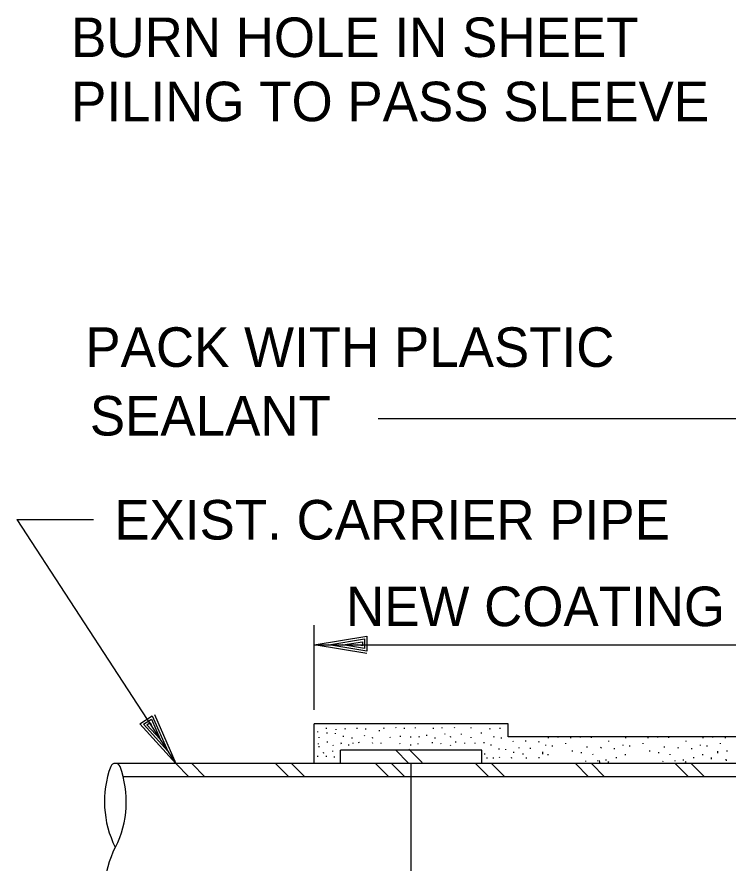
# Model space of a CAD drawing. Extents: x 22411.4 to 22495.4, y 22369.6 to 22415.
# Drawn here: x 22423.849 to 22427.205, y 22392.769 to 22396.764 of the extents above; entities that cross this region are included whole.
import ezdxf

# ---------------------------------------------------------------- set-up
doc = ezdxf.new("R2010")
doc.units = 0
for name, color, linetype in [('Level 1', 7, 'Continuous'), ('Level 2', 7, 'Continuous'), ('Level 4', 7, 'Continuous'), ('Level 8', 7, 'Continuous')]:
    doc.layers.add(name, color=color, linetype=linetype)

msp = doc.modelspace()

# ---------------------------------------------------------------- linework, layer by layer
at = {"layer": 'Level 1'}
for p, q in [((22425.251, 22393.4924), (22425.251, 22393.8919)), ((22425.251, 22393.7989), (22427.4581, 22393.7989)), ((22426.3069, 22393.7989), (22426.3069, 22393.7989)), ((22426.3762, 22393.7989), (22426.3762, 22393.7989))]:
    msp.add_line(p, q, dxfattribs=at)
msp.add_lwpolyline([(22425.5004, 22393.7575), (22425.251, 22393.7989), (22425.5004, 22393.8402), (22425.5004, 22393.7695), (22425.3204, 22393.7989), (22425.4897, 22393.8269), (22425.4897, 22393.7815), (22425.387, 22393.7989), (22425.479, 22393.8135), (22425.479, 22393.7949), (22425.4564, 22393.7989)], dxfattribs=at)
for centre, radius, start, end in [((22424.3136, 22393.2159), 0.0235, 20.1936, 159.8064), ((22424.7418, 22393.0584), 0.4798, 159.8064, 206.6071), ((22423.8853, 22393.0584), 0.4798, 333.3929, 20.1936), ((22424.7418, 22392.6286), 0.4798, 153.3929, 200.1919)]:
    msp.add_arc(centre, radius, start, end, dxfattribs=at)
at = {"layer": 'Level 2'}
for p, q in [((22425.5528, 22394.8684), (22427.4697, 22394.8684)), ((22423.8491, 22394.3903), (22424.2107, 22394.3903)), ((22423.8491, 22394.3903), (22424.5994, 22393.2392)), ((22426.1677, 22393.4267), (22425.251, 22393.4267)), ((22425.251, 22393.2392), (22425.251, 22393.4267)), ((22426.1677, 22393.3642), (22426.1677, 22393.4267)), ((22426.3069, 22393.3642), (22426.1677, 22393.3642)), ((22432.6119, 22393.3642), (22426.3069, 22393.3642)), ((22425.376, 22393.2392), (22425.376, 22393.3017)), ((22426.0427, 22393.3017), (22425.376, 22393.3017)), ((22426.0427, 22393.2392), (22426.0427, 22393.3017)), ((22429.4594, 22393.2392), (22424.3136, 22393.2392)), ((22425.7094, 22392.4475), (22425.7094, 22393.2392)), ((22429.4594, 22393.1767), (22424.3503, 22393.1767))]:
    msp.add_line(p, q, dxfattribs=at)
for points in [[(22424.4979, 22393.4707), (22424.5994, 22393.2392), (22424.4286, 22393.4255), (22424.4878, 22393.4641), (22424.5615, 22393.2973), (22424.4456, 22393.4239), (22424.4836, 22393.4486), (22424.5251, 22393.3532), (22424.4626, 22393.4222), (22424.4782, 22393.4324), (22424.4873, 22393.4112)], [(22427.1329, 22393.3613), (22427.1327, 22393.3642)]]:
    msp.add_lwpolyline(points, dxfattribs=at)
at = {"layer": 'Level 8'}
for p, q in [((22425.2696, 22393.3864), (22425.2693, 22393.3904)), ((22425.31, 22393.4025), (22425.3096, 22393.4066)), ((22425.3557, 22393.3971), (22425.3553, 22393.4012)), ((22425.3987, 22393.3998), (22425.3983, 22393.4039)), ((22425.4551, 22393.4025), (22425.4548, 22393.4066)), ((22425.4954, 22393.3998), (22425.4951, 22393.4039)), ((22425.56, 22393.3918), (22425.5596, 22393.3958)), ((22425.5815, 22393.4025), (22425.5811, 22393.4066)), ((22425.6379, 22393.4052), (22425.6376, 22393.4093)), ((22425.6782, 22393.4025), (22425.6779, 22393.4066)), ((22425.7293, 22393.4052), (22425.729, 22393.4093)), ((22425.8153, 22393.4025), (22425.815, 22393.4066)), ((22425.8556, 22393.4052), (22425.8553, 22393.4093)), ((22425.9147, 22393.4052), (22425.9144, 22393.4093)), ((22425.9927, 22393.4052), (22425.9924, 22393.4093)), ((22426.0814, 22393.3998), (22426.0811, 22393.4039)), ((22426.1298, 22393.4025), (22426.1295, 22393.4066)), ((22425.275, 22393.3595), (22425.2747, 22393.3635)), ((22425.3126, 22393.381), (22425.3123, 22393.3851)), ((22425.353, 22393.3783), (22425.3526, 22393.3824)), ((22425.3906, 22393.3648), (22425.3903, 22393.3689)), ((22425.4309, 22393.3568), (22425.4306, 22393.3609)), ((22425.4901, 22393.3675), (22425.4897, 22393.3716)), ((22425.5277, 22393.3568), (22425.5274, 22393.3609)), ((22425.611, 22393.3595), (22425.6107, 22393.3636)), ((22425.6594, 22393.3649), (22425.6591, 22393.369)), ((22425.7078, 22393.3622), (22425.7074, 22393.3663)), ((22425.7481, 22393.3622), (22425.7478, 22393.3663)), ((22425.783, 22393.3702), (22425.7827, 22393.3743)), ((22425.8233, 22393.3568), (22425.823, 22393.3609)), ((22425.869, 22393.3756), (22425.8687, 22393.3797)), ((22425.8959, 22393.3622), (22425.8956, 22393.3663)), ((22425.947, 22393.3756), (22425.9467, 22393.3797)), ((22425.9927, 22393.3595), (22425.9924, 22393.3636)), ((22426.0411, 22393.381), (22426.0408, 22393.3851)), ((22426.1002, 22393.3622), (22426.0999, 22393.3663)), ((22426.1352, 22393.3568), (22426.1348, 22393.3609)), ((22426.3575, 22393.3585), (22426.3572, 22393.3626)), ((22426.4627, 22393.3585), (22426.4623, 22393.3626)), ((22426.5605, 22393.3598), (22426.5602, 22393.3639)), ((22426.7223, 22393.3585), (22426.7219, 22393.3626)), ((22426.8274, 22393.3585), (22426.8271, 22393.3626)), ((22426.9253, 22393.3598), (22426.9249, 22393.3639)), ((22427.087, 22393.3585), (22427.0867, 22393.3626)), ((22427.1922, 22393.3585), (22427.1918, 22393.3626)), ((22425.2723, 22393.3299), (22425.272, 22393.334)), ((22425.275, 22393.3164), (22425.2747, 22393.3205)), ((22425.3153, 22393.3379), (22425.315, 22393.342)), ((22425.3422, 22393.3218), (22425.3419, 22393.3259)), ((22425.3798, 22393.3326), (22425.3795, 22393.3366)), ((22425.3798, 22393.3299), (22425.3795, 22393.334)), ((22425.4148, 22393.3245), (22425.4145, 22393.3286)), ((22425.4363, 22393.3326), (22425.436, 22393.3367)), ((22425.4632, 22393.3353), (22425.4628, 22393.3393)), ((22425.5277, 22393.3326), (22425.5274, 22393.3367)), ((22425.568, 22393.3326), (22425.5677, 22393.3367)), ((22425.6567, 22393.3299), (22425.6564, 22393.334)), ((22425.7078, 22393.3245), (22425.7074, 22393.3286)), ((22425.7427, 22393.3299), (22425.7424, 22393.334)), ((22425.8099, 22393.3353), (22425.8096, 22393.3394)), ((22425.8502, 22393.3299), (22425.8499, 22393.334)), ((22425.8959, 22393.3218), (22425.8956, 22393.3259)), ((22425.9201, 22393.338), (22425.9198, 22393.3421)), ((22425.9631, 22393.3326), (22425.9628, 22393.3367)), ((22426.0115, 22393.3326), (22426.0112, 22393.3367)), ((22426.0545, 22393.3353), (22426.0542, 22393.3394)), ((22426.0868, 22393.3245), (22426.0865, 22393.3286)), ((22426.1244, 22393.3057), (22426.1241, 22393.3098)), ((22426.1916, 22393.3407), (22426.1913, 22393.3447)), ((22426.2185, 22393.3111), (22426.2182, 22393.3152)), ((22426.2507, 22393.3433), (22426.2504, 22393.3474)), ((22426.2722, 22393.3084), (22426.2719, 22393.3125)), ((22426.3126, 22393.338), (22426.3122, 22393.3421)), ((22426.3453, 22393.3232), (22426.3449, 22393.3272)), ((22426.3765, 22393.3191), (22426.3762, 22393.3232)), ((22426.4396, 22393.3313), (22426.4393, 22393.3354)), ((22426.5402, 22393.315), (22426.5398, 22393.3191)), ((22426.6048, 22393.3117), (22426.6066, 22393.3156)), ((22426.6421, 22393.3422), (22426.6418, 22393.3462)), ((22426.6693, 22393.3068), (22426.6689, 22393.3109)), ((22426.71, 22393.3232), (22426.7097, 22393.3272)), ((22426.7413, 22393.3191), (22426.7409, 22393.3232)), ((22426.8043, 22393.3313), (22426.804, 22393.3354)), ((22426.9049, 22393.315), (22426.9046, 22393.3191)), ((22426.9695, 22393.3117), (22426.9713, 22393.3156)), ((22427.0068, 22393.3422), (22427.0065, 22393.3462)), ((22427.034, 22393.3068), (22427.0337, 22393.3109)), ((22427.0748, 22393.3232), (22427.0744, 22393.3272)), ((22427.106, 22393.3191), (22427.1057, 22393.3232)), ((22427.1691, 22393.3313), (22427.1688, 22393.3354)), ((22424.5615, 22393.2973), (22424.5615, 22393.2973)), ((22425.2696, 22393.2707), (22425.2693, 22393.2748)), ((22425.2965, 22393.2868), (22425.2962, 22393.2909)), ((22425.31, 22393.2707), (22425.3096, 22393.2748)), ((22425.3395, 22393.2949), (22425.3392, 22393.299)), ((22425.3476, 22393.268), (22425.3473, 22393.2721)), ((22426.0572, 22393.2815), (22426.0569, 22393.2856)), ((22426.1271, 22393.2654), (22426.1268, 22393.2694)), ((22426.1567, 22393.303), (22426.1563, 22393.3071)), ((22426.1943, 22393.2896), (22426.194, 22393.2937)), ((22426.2373, 22393.2815), (22426.237, 22393.2856)), ((22426.314, 22393.2647), (22426.3137, 22393.2688)), ((22426.3309, 22393.2833), (22426.3309, 22393.2933)), ((22426.3557, 22393.2781), (22426.3564, 22393.2829)), ((22426.4708, 22393.296), (22426.4705, 22393.3001)), ((22426.513, 22393.2878), (22426.5127, 22393.2919)), ((22426.5673, 22393.2797), (22426.567, 22393.2837)), ((22426.6788, 22393.2647), (22426.6784, 22393.2688)), ((22426.7204, 22393.2781), (22426.7212, 22393.2829)), ((22426.8356, 22393.296), (22426.8353, 22393.3001)), ((22426.8778, 22393.2878), (22426.8774, 22393.2919)), ((22426.9321, 22393.2797), (22426.9318, 22393.2837)), ((22427.0435, 22393.2647), (22427.0432, 22393.2688)), ((22427.0852, 22393.2781), (22427.0859, 22393.2829)), ((22427.1562, 22393.2882), (22427.1555, 22393.2964)), ((22427.2003, 22393.296), (22427.2, 22393.3001)), ((22424.5994, 22393.2392), (22424.5994, 22393.2392)), ((22426.068, 22393.2627), (22426.0676, 22393.2667)), ((22426.0975, 22393.2627), (22426.0972, 22393.2667)), ((22426.1835, 22393.2627), (22426.1832, 22393.2668)), ((22426.2534, 22393.2627), (22426.2531, 22393.2668)), ((22426.5328, 22393.2477), (22426.5331, 22393.2513)), ((22426.5904, 22393.2497), (22426.5901, 22393.2538)), ((22426.5991, 22393.2443), (22426.5984, 22393.2525)), ((22426.6298, 22393.2538), (22426.6295, 22393.2579)), ((22426.6392, 22393.2435), (22426.6417, 22393.2477)), ((22426.8975, 22393.2477), (22426.8978, 22393.2513)), ((22426.9552, 22393.2497), (22426.9548, 22393.2538)), ((22426.9946, 22393.2538), (22426.9943, 22393.2579)), ((22427.0039, 22393.2435), (22427.0064, 22393.2477)), ((22427.1266, 22393.2586), (22427.1259, 22393.2667)), ((22427.1968, 22393.2509), (22427.1962, 22393.2591))]:
    msp.add_line(p, q, dxfattribs=at)
for points in [[(22426.4034, 22393.3613), (22426.4032, 22393.3642)], [(22426.508, 22393.3617), (22426.508, 22393.3642)], [(22426.8728, 22393.3617), (22426.8728, 22393.3642)], [(22425.6974, 22393.2403), (22425.6348, 22393.3028)], [(22425.7609, 22393.2435), (22425.6983, 22393.3061)], [(22424.6609, 22393.1767), (22424.5984, 22393.2392)], [(22424.7364, 22393.1767), (22424.6739, 22393.2392)], [(22425.1323, 22393.1767), (22425.0698, 22393.2392)], [(22425.2078, 22393.1767), (22425.1453, 22393.2392)], [(22425.6038, 22393.1767), (22425.5413, 22393.2392)], [(22425.6792, 22393.1767), (22425.6167, 22393.2392)], [(22426.0752, 22393.1767), (22426.0127, 22393.2392)], [(22426.1506, 22393.1767), (22426.0881, 22393.2392)], [(22426.5466, 22393.1767), (22426.4841, 22393.2392)], [(22426.622, 22393.1767), (22426.5595, 22393.2392)], [(22427.018, 22393.1767), (22426.9555, 22393.2392)], [(22427.0934, 22393.1767), (22427.0309, 22393.2392)]]:
    msp.add_lwpolyline(points, dxfattribs=at)

# ---------------------------------------------------------------- texts
at = {"layer": 'Level 4'}
for s, height, p in [('BURN HOLE IN SHEET', 0.186667, (22424.1047, 22396.5743)), ('PILING TO PASS SLEEVE', 0.186667, (22424.1047, 22396.2713)), ('PACK WITH PLASTIC', 0.186667, (22424.1719, 22395.1115)), ('SEALANT', 0.18667, (22424.1931, 22394.7874)), ('EXIST. CARRIER PIPE', 0.186667, (22424.3084, 22394.2964)), ('NEW COATING', 0.186667, (22425.4017, 22393.8874))]:
    msp.add_text(s, height=height, dxfattribs=at).set_placement(p)

doc.saveas('drawing.dxf')
